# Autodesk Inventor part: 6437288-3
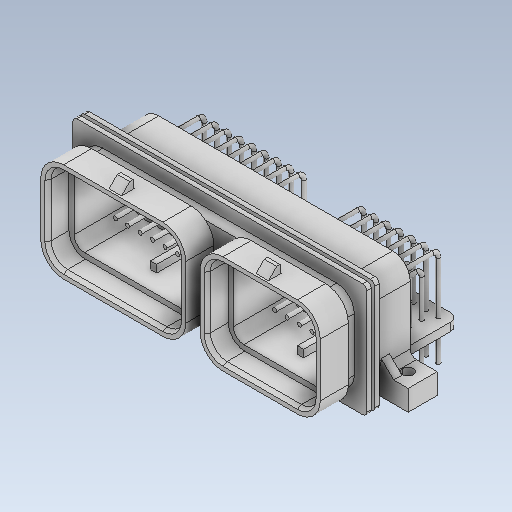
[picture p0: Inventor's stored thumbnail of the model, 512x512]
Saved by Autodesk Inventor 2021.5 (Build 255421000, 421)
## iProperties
Created: 2024-12
Part Number: 6437288-3
Checked By: TraceParts S.A.
Material: Generic
Catalog Web Link: www.traceparts.com
Document SubType Name: Modeling
Designer: TraceParts
Density: 1 g/cm^3
Appearance: Default
Company: TraceParts S.A.
Author: TraceParts
SUPPLIER_NAME: RS Components
SUPPLIER: TE Connectivity
DESIGN: TE Connectivity SUPERSEAL Series, 4 Row 60 Way Through Hole Socket Wire to Board Connector, with Solder Termination
REFERENCE: 6437288-3
Buy_Now: https://uk.rs-online.com/web/p/products/7199680?cm_mmc=en-ds-_-mcad-_-traceparts-_-7199680'
rs_stock_number: 7199680
allied_stock_number: 70288113
TraceParts.PartVersion: 1.0.6
TraceParts.PartStatus: Published
TraceParts.PartNumber: 10-23082019-073984
TraceParts.PartLanguage: en
TraceParts.InstanceId: 10-23082019-073984S91WPDGZSGOE0H4RXXMI1Y20
TraceParts.PartTitle: TE Connectivity SUPERSEAL Series, 4 Row 60 Way Through Hole Socket Wire to Board Connector, with Solder Termination
TRACEPARTS: TRACEPARTS
TraceParts.ClassPath: RS_COMPONENTS:10-23082019-073984
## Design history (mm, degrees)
feature "6437288-3"
body "Solid1"
